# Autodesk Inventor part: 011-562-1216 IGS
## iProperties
Created: 2010-02
Part Number: 011-562-1216 IGS
Document SubType Name: Modeling
Designer: Alex_Cyril
Norme de conversion: IGES 5.3
Nom du fichier: \\Bisondraw\drawings\SOLIDWORKS CUSTOMER ASSY\011-562-1216\011-562-1216.IGS
Préprocesseur: SolidWorks 2009
Postprocesseur: Build: 391, Release: 11 SP3 - Date: Tue 06/05/2007
Unités envoyées: MM
Incertitude: 1e-08
Author: Alex_Cyril
